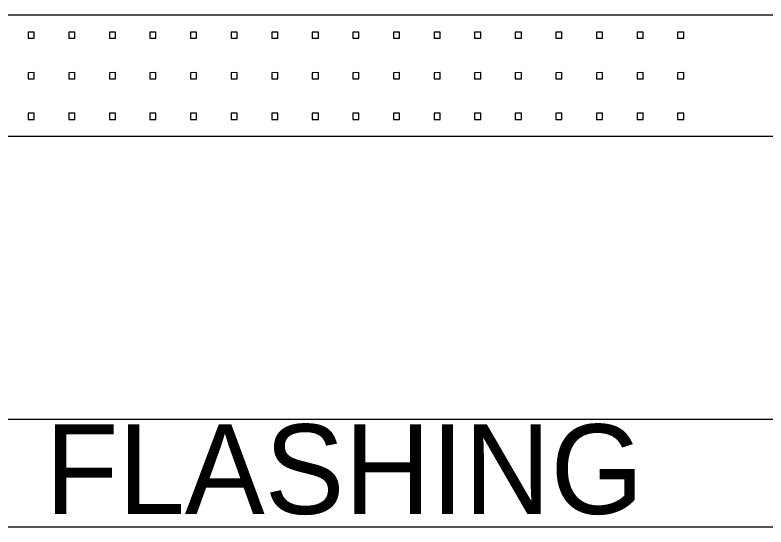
# Model space of a CAD drawing. Extents: x 15 to 764, y 7 to 487.
# Drawn here: x 581.31 to 610.69, y 163.97 to 183.98 of the extents above; entities that cross this region are included whole.
import ezdxf

# ---------------------------------------------------------------- set-up
doc = ezdxf.new("R2010")
doc.units = 0
doc.layers.add('Default', color=7, linetype='Continuous')
doc.layers.add('TextStructures', color=7, linetype='Continuous')

msp = doc.modelspace()

# ---------------------------------------------------------------- linework, layer by layer
at = {"layer": 'Default'}
for p, q in [((756.61, 183.984), (462.687, 183.984)), ((462.687, 179.246), (756.61, 179.246)), ((462.687, 168.178), (756.61, 168.178)), ((462.687, 163.965), (756.61, 163.965))]:
    msp.add_line(p, q, dxfattribs=at)
for points in [[(582.06, 183.08), (582.06, 183.319), (581.823, 183.318), (581.823, 183.08), (582.06, 183.08)], [(582.06, 183.08), (582.06, 183.319), (581.823, 183.318), (581.823, 183.08), (582.06, 183.08)], [(583.646, 183.08), (583.646, 183.319), (583.41, 183.318), (583.41, 183.08), (583.646, 183.08)], [(583.646, 183.08), (583.646, 183.319), (583.41, 183.318), (583.41, 183.08), (583.646, 183.08)], [(585.236, 183.08), (585.236, 183.319), (584.999, 183.318), (584.999, 183.08), (585.236, 183.08)], [(585.236, 183.08), (585.236, 183.319), (584.999, 183.318), (584.999, 183.08), (585.236, 183.08)], [(586.822, 183.08), (586.822, 183.319), (586.586, 183.318), (586.586, 183.08), (586.822, 183.08)], [(586.822, 183.08), (586.822, 183.319), (586.586, 183.318), (586.586, 183.08), (586.822, 183.08)], [(588.412, 183.08), (588.412, 183.319), (588.175, 183.318), (588.175, 183.08), (588.412, 183.08)], [(588.412, 183.08), (588.412, 183.319), (588.175, 183.318), (588.175, 183.08), (588.412, 183.08)], [(589.998, 183.08), (589.998, 183.319), (589.762, 183.318), (589.762, 183.08), (589.998, 183.08)], [(589.998, 183.08), (589.998, 183.319), (589.762, 183.318), (589.762, 183.08), (589.998, 183.08)], [(591.588, 183.08), (591.588, 183.319), (591.352, 183.318), (591.352, 183.08), (591.588, 183.08)], [(591.588, 183.08), (591.588, 183.319), (591.352, 183.318), (591.352, 183.08), (591.588, 183.08)], [(593.175, 183.08), (593.175, 183.319), (592.938, 183.318), (592.938, 183.08), (593.175, 183.08)], [(593.175, 183.08), (593.175, 183.319), (592.938, 183.318), (592.938, 183.08), (593.175, 183.08)], [(594.764, 183.08), (594.764, 183.319), (594.528, 183.318), (594.528, 183.08), (594.764, 183.08)], [(594.764, 183.08), (594.764, 183.319), (594.528, 183.318), (594.528, 183.08), (594.764, 183.08)], [(596.351, 183.08), (596.351, 183.319), (596.114, 183.318), (596.114, 183.08), (596.351, 183.08)], [(596.351, 183.08), (596.351, 183.319), (596.114, 183.318), (596.114, 183.08), (596.351, 183.08)], [(597.941, 183.08), (597.941, 183.319), (597.704, 183.318), (597.704, 183.08), (597.941, 183.08)], [(597.941, 183.08), (597.941, 183.319), (597.704, 183.318), (597.704, 183.08), (597.941, 183.08)], [(599.527, 183.08), (599.527, 183.319), (599.29, 183.318), (599.29, 183.08), (599.527, 183.08)], [(599.527, 183.08), (599.527, 183.319), (599.29, 183.318), (599.29, 183.08), (599.527, 183.08)], [(601.117, 183.08), (601.117, 183.319), (600.88, 183.318), (600.88, 183.08), (601.117, 183.08)], [(601.117, 183.08), (601.117, 183.319), (600.88, 183.318), (600.88, 183.08), (601.117, 183.08)], [(602.703, 183.08), (602.703, 183.319), (602.466, 183.318), (602.466, 183.08), (602.703, 183.08)], [(602.703, 183.08), (602.703, 183.319), (602.466, 183.318), (602.466, 183.08), (602.703, 183.08)], [(604.293, 183.08), (604.293, 183.319), (604.056, 183.318), (604.056, 183.08), (604.293, 183.08)], [(604.293, 183.08), (604.293, 183.319), (604.056, 183.318), (604.056, 183.08), (604.293, 183.08)], [(605.879, 183.08), (605.879, 183.319), (605.643, 183.318), (605.643, 183.08), (605.879, 183.08)], [(605.879, 183.08), (605.879, 183.319), (605.643, 183.318), (605.643, 183.08), (605.879, 183.08)], [(607.469, 183.08), (607.469, 183.319), (607.232, 183.318), (607.232, 183.08), (607.469, 183.08)], [(607.469, 183.08), (607.469, 183.319), (607.232, 183.318), (607.232, 183.08), (607.469, 183.08)], [(582.06, 181.491), (582.06, 181.73), (581.823, 181.729), (581.823, 181.491), (582.06, 181.491)], [(582.06, 181.491), (582.06, 181.73), (581.823, 181.729), (581.823, 181.491), (582.06, 181.491)], [(583.646, 181.491), (583.646, 181.73), (583.41, 181.729), (583.41, 181.491), (583.646, 181.491)], [(583.646, 181.491), (583.646, 181.73), (583.41, 181.729), (583.41, 181.491), (583.646, 181.491)], [(585.236, 181.491), (585.236, 181.73), (584.999, 181.729), (584.999, 181.491), (585.236, 181.491)], [(585.236, 181.491), (585.236, 181.73), (584.999, 181.729), (584.999, 181.491), (585.236, 181.491)], [(586.822, 181.491), (586.822, 181.73), (586.586, 181.729), (586.586, 181.491), (586.822, 181.491)], [(586.822, 181.491), (586.822, 181.73), (586.586, 181.729), (586.586, 181.491), (586.822, 181.491)], [(588.412, 181.491), (588.412, 181.73), (588.175, 181.729), (588.175, 181.491), (588.412, 181.491)], [(588.412, 181.491), (588.412, 181.73), (588.175, 181.729), (588.175, 181.491), (588.412, 181.491)], [(589.998, 181.491), (589.998, 181.73), (589.762, 181.729), (589.762, 181.491), (589.998, 181.491)], [(589.998, 181.491), (589.998, 181.73), (589.762, 181.729), (589.762, 181.491), (589.998, 181.491)], [(591.588, 181.491), (591.588, 181.73), (591.352, 181.729), (591.352, 181.491), (591.588, 181.491)], [(591.588, 181.491), (591.588, 181.73), (591.352, 181.729), (591.352, 181.491), (591.588, 181.491)], [(593.175, 181.491), (593.175, 181.73), (592.938, 181.729), (592.938, 181.491), (593.175, 181.491)], [(593.175, 181.491), (593.175, 181.73), (592.938, 181.729), (592.938, 181.491), (593.175, 181.491)], [(594.764, 181.491), (594.764, 181.73), (594.528, 181.729), (594.528, 181.491), (594.764, 181.491)], [(594.764, 181.491), (594.764, 181.73), (594.528, 181.729), (594.528, 181.491), (594.764, 181.491)], [(596.351, 181.491), (596.351, 181.73), (596.114, 181.729), (596.114, 181.491), (596.351, 181.491)], [(596.351, 181.491), (596.351, 181.73), (596.114, 181.729), (596.114, 181.491), (596.351, 181.491)], [(597.941, 181.491), (597.941, 181.73), (597.704, 181.729), (597.704, 181.491), (597.941, 181.491)], [(597.941, 181.491), (597.941, 181.73), (597.704, 181.729), (597.704, 181.491), (597.941, 181.491)], [(599.527, 181.491), (599.527, 181.73), (599.29, 181.729), (599.29, 181.491), (599.527, 181.491)], [(599.527, 181.491), (599.527, 181.73), (599.29, 181.729), (599.29, 181.491), (599.527, 181.491)], [(601.117, 181.491), (601.117, 181.73), (600.88, 181.729), (600.88, 181.491), (601.117, 181.491)], [(601.117, 181.491), (601.117, 181.73), (600.88, 181.729), (600.88, 181.491), (601.117, 181.491)], [(602.703, 181.491), (602.703, 181.73), (602.466, 181.729), (602.466, 181.491), (602.703, 181.491)], [(602.703, 181.491), (602.703, 181.73), (602.466, 181.729), (602.466, 181.491), (602.703, 181.491)], [(604.293, 181.491), (604.293, 181.73), (604.056, 181.729), (604.056, 181.491), (604.293, 181.491)], [(604.293, 181.491), (604.293, 181.73), (604.056, 181.729), (604.056, 181.491), (604.293, 181.491)], [(605.879, 181.491), (605.879, 181.73), (605.643, 181.729), (605.643, 181.491), (605.879, 181.491)], [(605.879, 181.491), (605.879, 181.73), (605.643, 181.729), (605.643, 181.491), (605.879, 181.491)], [(607.469, 181.491), (607.469, 181.73), (607.232, 181.729), (607.232, 181.491), (607.469, 181.491)], [(607.469, 181.491), (607.469, 181.73), (607.232, 181.729), (607.232, 181.491), (607.469, 181.491)], [(582.06, 179.904), (582.06, 180.143), (581.823, 180.142), (581.823, 179.904), (582.06, 179.904)], [(582.06, 179.904), (582.06, 180.143), (581.823, 180.142), (581.823, 179.904), (582.06, 179.904)], [(583.646, 179.904), (583.646, 180.143), (583.41, 180.142), (583.41, 179.904), (583.646, 179.904)], [(583.646, 179.904), (583.646, 180.143), (583.41, 180.142), (583.41, 179.904), (583.646, 179.904)], [(585.236, 179.904), (585.236, 180.143), (584.999, 180.142), (584.999, 179.904), (585.236, 179.904)], [(585.236, 179.904), (585.236, 180.143), (584.999, 180.142), (584.999, 179.904), (585.236, 179.904)], [(586.822, 179.904), (586.822, 180.143), (586.586, 180.142), (586.586, 179.904), (586.822, 179.904)], [(586.822, 179.904), (586.822, 180.143), (586.586, 180.142), (586.586, 179.904), (586.822, 179.904)], [(588.412, 179.904), (588.412, 180.143), (588.175, 180.142), (588.175, 179.904), (588.412, 179.904)], [(588.412, 179.904), (588.412, 180.143), (588.175, 180.142), (588.175, 179.904), (588.412, 179.904)], [(589.998, 179.904), (589.998, 180.143), (589.762, 180.142), (589.762, 179.904), (589.998, 179.904)], [(589.998, 179.904), (589.998, 180.143), (589.762, 180.142), (589.762, 179.904), (589.998, 179.904)], [(591.588, 179.904), (591.588, 180.143), (591.352, 180.142), (591.352, 179.904), (591.588, 179.904)], [(591.588, 179.904), (591.588, 180.143), (591.352, 180.142), (591.352, 179.904), (591.588, 179.904)], [(593.175, 179.904), (593.175, 180.143), (592.938, 180.142), (592.938, 179.904), (593.175, 179.904)], [(593.175, 179.904), (593.175, 180.143), (592.938, 180.142), (592.938, 179.904), (593.175, 179.904)], [(594.764, 179.904), (594.764, 180.143), (594.528, 180.142), (594.528, 179.904), (594.764, 179.904)], [(594.764, 179.904), (594.764, 180.143), (594.528, 180.142), (594.528, 179.904), (594.764, 179.904)], [(596.351, 179.904), (596.351, 180.143), (596.114, 180.142), (596.114, 179.904), (596.351, 179.904)], [(596.351, 179.904), (596.351, 180.143), (596.114, 180.142), (596.114, 179.904), (596.351, 179.904)], [(597.941, 179.904), (597.941, 180.143), (597.704, 180.142), (597.704, 179.904), (597.941, 179.904)], [(597.941, 179.904), (597.941, 180.143), (597.704, 180.142), (597.704, 179.904), (597.941, 179.904)], [(599.527, 179.904), (599.527, 180.143), (599.29, 180.142), (599.29, 179.904), (599.527, 179.904)], [(599.527, 179.904), (599.527, 180.143), (599.29, 180.142), (599.29, 179.904), (599.527, 179.904)], [(601.117, 179.904), (601.117, 180.143), (600.88, 180.142), (600.88, 179.904), (601.117, 179.904)], [(601.117, 179.904), (601.117, 180.143), (600.88, 180.142), (600.88, 179.904), (601.117, 179.904)], [(602.703, 179.904), (602.703, 180.143), (602.466, 180.142), (602.466, 179.904), (602.703, 179.904)], [(602.703, 179.904), (602.703, 180.143), (602.466, 180.142), (602.466, 179.904), (602.703, 179.904)], [(604.293, 179.904), (604.293, 180.143), (604.056, 180.142), (604.056, 179.904), (604.293, 179.904)], [(604.293, 179.904), (604.293, 180.143), (604.056, 180.142), (604.056, 179.904), (604.293, 179.904)], [(605.879, 179.904), (605.879, 180.143), (605.643, 180.142), (605.643, 179.904), (605.879, 179.904)], [(605.879, 179.904), (605.879, 180.143), (605.643, 180.142), (605.643, 179.904), (605.879, 179.904)], [(607.469, 179.904), (607.469, 180.143), (607.232, 180.142), (607.232, 179.904), (607.469, 179.904)], [(607.469, 179.904), (607.469, 180.143), (607.232, 180.142), (607.232, 179.904), (607.469, 179.904)]]:
    msp.add_lwpolyline(points, dxfattribs=at)

# ---------------------------------------------------------------- texts
at = {"layer": 'TextStructures'}
msp.add_text('FLASHING', height=3.5, rotation=0.0007, dxfattribs=at).set_placement((582.492, 164.476))

doc.saveas('drawing.dxf')
